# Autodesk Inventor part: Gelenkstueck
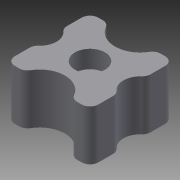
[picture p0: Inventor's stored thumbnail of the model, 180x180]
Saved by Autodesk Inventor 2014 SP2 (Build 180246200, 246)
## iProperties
Created: 2015-06
Part Number: Gelenkstueck
Material: Generisch
Document SubType Name: Modeling
Designer: e_krauts
Density: 1 g/cm^3
Appearance: Vorgabe
Author: e_krauts
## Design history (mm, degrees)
sketch "Skizze1"
  geometry: L1 (-25, 25)-(25, 25); L2 (25, 25)-(25, -25); L3 (25, -25)-(-25, -25); L4 (-25, -25)-(-25, 25); L5 (-25, 25)-(25, -25); L6 (25, 25)-(-25, -25); 1 further point
  constraints: 12 end point, 2 midpoint, 2 parallel, 1 horizontal, 1 perpendicular
  dimensions: "d0" = 50 distance between parallel lines of L2 L4; "d1" = 50 distance between parallel lines of L3 L1
extrude "Extrusion1" new body sketch "Skizze1" distance "d2" = 30; taper "d3" = 0 deg
sketch "Skizze2"
  geometry: L1 (25, -25)-(25, 25) reference; L2 (0, 48)-(0, -50) reference; L3 (-49, 0)-(66, 0) reference; C1 r 15 at (0, 30); C2 r 10 at (-30, 0); C3 r 15 at (0, -30); C4 r 10 at (30, 0); 1 further point
  constraints: 4 centre point, 4 end point, 2 point on line, 2 symmetric about line, 1 horizontal, 1 parallel, 1 perpendicular, 1 vertical, 2 other
  dimensions: "d4" = 30 diameter of C1; "d5" = 20 diameter of C2; "d6" = 60 diameter of C1.centre L3; "d7" = 60 diameter of C2.centre L2
extrude "Extrusion2" cut sketch "Skizze2" stored distance "d8" = 30; taper "d9" = 0 deg
fillet "Rundung1" dims "d10" = 5
sketch "Skizze3"
  geometry: 2 further points
  constraints: 1 coincident
hole "Bohrung1" sketch "Skizze3" at (0, 0) diameter "d11" = 11; stored, may be unused: countersink angle "d15" = 90 deg, drill point angle "d17" = 118 deg; dims "d12" = 6, "d13" = 18, "d14" = 10.6, "d16" = 8
node "Volumenkörper1"
